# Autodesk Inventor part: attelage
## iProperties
Shininess: 64.0
Length Units: 11269
Angle Units: 11279
Time Units: 11290
Mass Units: 11283
Length Display Precision: 3
Angle Display Precision: 2
Compacted: True
Part Number: attelage
Document SubType Name: Modeling
Created: 2004-12
Material: Par défaut
Designer: LEGERET Philippe
Density: 0.0
Volumn: 0.0
Area: 0.0
PropertySet Name: Model Information
Control State: 0
Master: False
Checked Out: False
Author: LEGERET Philippe
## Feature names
1. Révolution1 [Revolution]
2. Chanfrein1 [Chamfer]
3. Extrusion1
4. Symétrie1 [Mirror]
5. Perçage1 [Hole]
6. Perçage2 [Hole]
7. Réseau circulaire1 [Circular Pattern]
8. Réseau circulaire2 [Circular Pattern]
9. Symétrie2 [Mirror]
10. Chanfrein2 [Chamfer]
11. Chanfrein3 [Chamfer]
